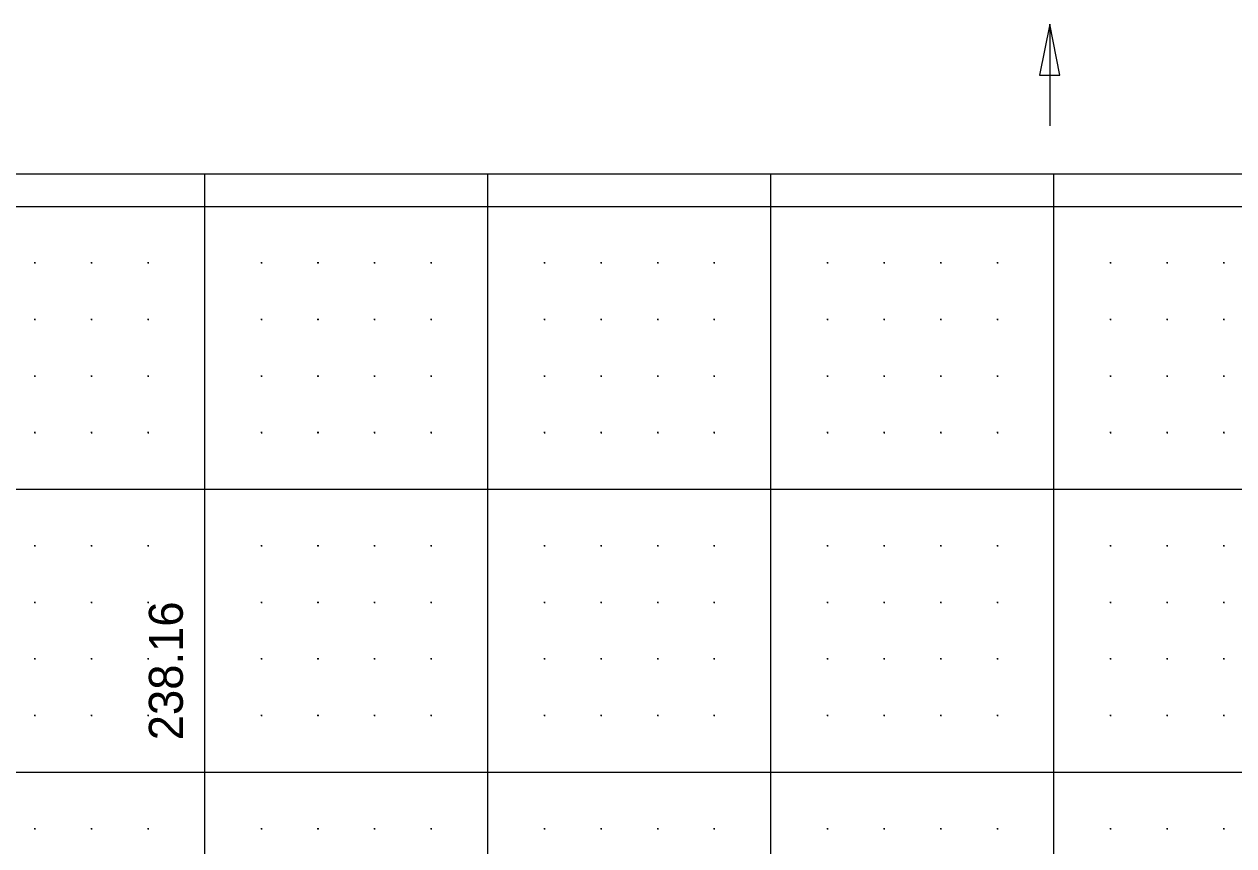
# Model space of a CAD drawing. Extents: x -80 to 80, y 222 to 253.
# Drawn here: x 36.81 to 58.18, y 238.7 to 253.22 of the extents above; entities that cross this region are included whole.
import ezdxf

# ---------------------------------------------------------------- set-up
doc = ezdxf.new("R2010")
doc.units = 0
for name, color, linetype in [('DSN_DRFT_XS Border Grid', 7, 'Continuous'), ('DSN_DRFT_XS Grid Major', 7, 'Continuous'), ('DSN_DRFT_XS Grid Minor', 7, 'Continuous'), ('DSN_RDWY_Flow Arrow', 7, 'Continuous'), ('DSN_RDWY_XS Annotation', 7, 'Continuous')]:
    doc.layers.add(name, color=color, linetype=linetype)

msp = doc.modelspace()

# ---------------------------------------------------------------- linework, layer by layer
at = {"layer": 'DSN_DRFT_XS Border Grid'}
msp.add_line((-77.5, 250.573), (77.5, 250.573), dxfattribs=at)
at = {"layer": 'DSN_DRFT_XS Grid Major'}
for p, q in [((40, 226), (40, 250.573)), ((45, 226), (45, 250.573)), ((50, 226), (50, 250.573)), ((55, 226), (55, 250.573)), ((-77.5, 250), (77.5, 250)), ((-77.5, 245), (77.5, 245)), ((-77.5, 240), (77.5, 240))]:
    msp.add_line(p, q, dxfattribs=at)
at = {"layer": 'DSN_DRFT_XS Grid Minor'}
for p, q in [((37.012, 249), (36.988, 249)), ((37, 249.012), (37, 248.988)), ((38.012, 249), (37.988, 249)), ((38, 249.012), (38, 248.988)), ((39.012, 249), (38.988, 249)), ((39, 249.012), (39, 248.988)), ((41.012, 249), (40.988, 249)), ((41, 249.012), (41, 248.988)), ((42.012, 249), (41.988, 249)), ((42, 249.012), (42, 248.988)), ((43.012, 249), (42.988, 249)), ((43, 249.012), (43, 248.988)), ((44.012, 249), (43.988, 249)), ((44, 249.012), (44, 248.988)), ((46.012, 249), (45.988, 249)), ((46, 249.012), (46, 248.988)), ((47.012, 249), (46.988, 249)), ((47, 249.012), (47, 248.988)), ((48.012, 249), (47.988, 249)), ((48, 249.012), (48, 248.988)), ((49.012, 249), (48.988, 249)), ((49, 249.012), (49, 248.988)), ((51.012, 249), (50.988, 249)), ((51, 249.012), (51, 248.988)), ((52.012, 249), (51.988, 249)), ((52, 249.012), (52, 248.988)), ((53.012, 249), (52.988, 249)), ((53, 249.012), (53, 248.988)), ((54.012, 249), (53.988, 249)), ((54, 249.012), (54, 248.988)), ((56.012, 249), (55.988, 249)), ((56, 249.012), (56, 248.988)), ((57.012, 249), (56.988, 249)), ((57, 249.012), (57, 248.988)), ((58.012, 249), (57.988, 249)), ((58, 249.012), (58, 248.988)), ((37.012, 248), (36.988, 248)), ((37, 248.012), (37, 247.988)), ((38.012, 248), (37.988, 248)), ((38, 248.012), (38, 247.988)), ((39.012, 248), (38.988, 248)), ((39, 248.012), (39, 247.988)), ((41.012, 248), (40.988, 248)), ((41, 248.012), (41, 247.988)), ((42.012, 248), (41.988, 248)), ((42, 248.012), (42, 247.988)), ((43.012, 248), (42.988, 248)), ((43, 248.012), (43, 247.988)), ((44.012, 248), (43.988, 248)), ((44, 248.012), (44, 247.988)), ((46.012, 248), (45.988, 248)), ((46, 248.012), (46, 247.988)), ((47.012, 248), (46.988, 248)), ((47, 248.012), (47, 247.988)), ((48.012, 248), (47.988, 248)), ((48, 248.012), (48, 247.988)), ((49.012, 248), (48.988, 248)), ((49, 248.012), (49, 247.988)), ((51.012, 248), (50.988, 248)), ((51, 248.012), (51, 247.988)), ((52.012, 248), (51.988, 248)), ((52, 248.012), (52, 247.988)), ((53.012, 248), (52.988, 248)), ((53, 248.012), (53, 247.988)), ((54.012, 248), (53.988, 248)), ((54, 248.012), (54, 247.988)), ((56.012, 248), (55.988, 248)), ((56, 248.012), (56, 247.988)), ((57.012, 248), (56.988, 248)), ((57, 248.012), (57, 247.988)), ((58.012, 248), (57.988, 248)), ((58, 248.012), (58, 247.988)), ((37.012, 247), (36.988, 247)), ((37, 247.012), (37, 246.988)), ((38.012, 247), (37.988, 247)), ((38, 247.012), (38, 246.988)), ((39.012, 247), (38.988, 247)), ((39, 247.012), (39, 246.988)), ((41.012, 247), (40.988, 247)), ((41, 247.012), (41, 246.988)), ((42.012, 247), (41.988, 247)), ((42, 247.012), (42, 246.988)), ((43.012, 247), (42.988, 247)), ((43, 247.012), (43, 246.988)), ((44.012, 247), (43.988, 247)), ((44, 247.012), (44, 246.988)), ((46.012, 247), (45.988, 247)), ((46, 247.012), (46, 246.988)), ((47.012, 247), (46.988, 247)), ((47, 247.012), (47, 246.988)), ((48.012, 247), (47.988, 247)), ((48, 247.012), (48, 246.988)), ((49.012, 247), (48.988, 247)), ((49, 247.012), (49, 246.988)), ((51.012, 247), (50.988, 247)), ((51, 247.012), (51, 246.988)), ((52.012, 247), (51.988, 247)), ((52, 247.012), (52, 246.988)), ((53.012, 247), (52.988, 247)), ((53, 247.012), (53, 246.988)), ((54.012, 247), (53.988, 247)), ((54, 247.012), (54, 246.988)), ((56.012, 247), (55.988, 247)), ((56, 247.012), (56, 246.988)), ((57.012, 247), (56.988, 247)), ((57, 247.012), (57, 246.988)), ((58.012, 247), (57.988, 247)), ((58, 247.012), (58, 246.988)), ((37.012, 246), (36.988, 246)), ((37, 246.012), (37, 245.988)), ((38.012, 246), (37.988, 246)), ((38, 246.012), (38, 245.988)), ((39.012, 246), (38.988, 246)), ((39, 246.012), (39, 245.988)), ((41.012, 246), (40.988, 246)), ((41, 246.012), (41, 245.988)), ((42.012, 246), (41.988, 246)), ((42, 246.012), (42, 245.988)), ((43.012, 246), (42.988, 246)), ((43, 246.012), (43, 245.988)), ((44.012, 246), (43.988, 246)), ((44, 246.012), (44, 245.988)), ((46.012, 246), (45.988, 246)), ((46, 246.012), (46, 245.988)), ((47.012, 246), (46.988, 246)), ((47, 246.012), (47, 245.988)), ((48.012, 246), (47.988, 246)), ((48, 246.012), (48, 245.988)), ((49.012, 246), (48.988, 246)), ((49, 246.012), (49, 245.988)), ((51.012, 246), (50.988, 246)), ((51, 246.012), (51, 245.988)), ((52.012, 246), (51.988, 246)), ((52, 246.012), (52, 245.988)), ((53.012, 246), (52.988, 246)), ((53, 246.012), (53, 245.988)), ((54.012, 246), (53.988, 246)), ((54, 246.012), (54, 245.988)), ((56.012, 246), (55.988, 246)), ((56, 246.012), (56, 245.988)), ((57.012, 246), (56.988, 246)), ((57, 246.012), (57, 245.988)), ((58.012, 246), (57.988, 246)), ((58, 246.012), (58, 245.988)), ((37.012, 244), (36.988, 244)), ((37, 244.012), (37, 243.988)), ((38.012, 244), (37.988, 244)), ((38, 244.012), (38, 243.988)), ((39.012, 244), (38.988, 244)), ((39, 244.012), (39, 243.988)), ((41.012, 244), (40.988, 244)), ((41, 244.012), (41, 243.988)), ((42.012, 244), (41.988, 244)), ((42, 244.012), (42, 243.988)), ((43.012, 244), (42.988, 244)), ((43, 244.012), (43, 243.988)), ((44.012, 244), (43.988, 244)), ((44, 244.012), (44, 243.988)), ((46.012, 244), (45.988, 244)), ((46, 244.012), (46, 243.988)), ((47.012, 244), (46.988, 244)), ((47, 244.012), (47, 243.988)), ((48.012, 244), (47.988, 244)), ((48, 244.012), (48, 243.988)), ((49.012, 244), (48.988, 244)), ((49, 244.012), (49, 243.988)), ((51.012, 244), (50.988, 244)), ((51, 244.012), (51, 243.988)), ((52.012, 244), (51.988, 244)), ((52, 244.012), (52, 243.988)), ((53.012, 244), (52.988, 244)), ((53, 244.012), (53, 243.988)), ((54.012, 244), (53.988, 244)), ((54, 244.012), (54, 243.988)), ((56.012, 244), (55.988, 244)), ((56, 244.012), (56, 243.988)), ((57.012, 244), (56.988, 244)), ((57, 244.012), (57, 243.988)), ((58.012, 244), (57.988, 244)), ((58, 244.012), (58, 243.988)), ((37.012, 243), (36.988, 243)), ((37, 243.012), (37, 242.988)), ((38.012, 243), (37.988, 243)), ((38, 243.012), (38, 242.988)), ((39.012, 243), (38.988, 243)), ((39, 243.012), (39, 242.988)), ((41.012, 243), (40.988, 243)), ((41, 243.012), (41, 242.988)), ((42.012, 243), (41.988, 243)), ((42, 243.012), (42, 242.988)), ((43.012, 243), (42.988, 243)), ((43, 243.012), (43, 242.988)), ((44.012, 243), (43.988, 243)), ((44, 243.012), (44, 242.988)), ((46.012, 243), (45.988, 243)), ((46, 243.012), (46, 242.988)), ((47.012, 243), (46.988, 243)), ((47, 243.012), (47, 242.988)), ((48.012, 243), (47.988, 243)), ((48, 243.012), (48, 242.988)), ((49.012, 243), (48.988, 243)), ((49, 243.012), (49, 242.988)), ((51.012, 243), (50.988, 243)), ((51, 243.012), (51, 242.988)), ((52.012, 243), (51.988, 243)), ((52, 243.012), (52, 242.988)), ((53.012, 243), (52.988, 243)), ((53, 243.012), (53, 242.988)), ((54.012, 243), (53.988, 243)), ((54, 243.012), (54, 242.988)), ((56.012, 243), (55.988, 243)), ((56, 243.012), (56, 242.988)), ((57.012, 243), (56.988, 243)), ((57, 243.012), (57, 242.988)), ((58.012, 243), (57.988, 243)), ((58, 243.012), (58, 242.988)), ((37.012, 242), (36.988, 242)), ((37, 242.012), (37, 241.988)), ((38.012, 242), (37.988, 242)), ((38, 242.012), (38, 241.988)), ((39.012, 242), (38.988, 242)), ((39, 242.012), (39, 241.988)), ((41.012, 242), (40.988, 242)), ((41, 242.012), (41, 241.988)), ((42.012, 242), (41.988, 242)), ((42, 242.012), (42, 241.988)), ((43.012, 242), (42.988, 242)), ((43, 242.012), (43, 241.988)), ((44.012, 242), (43.988, 242)), ((44, 242.012), (44, 241.988)), ((46.012, 242), (45.988, 242)), ((46, 242.012), (46, 241.988)), ((47.012, 242), (46.988, 242)), ((47, 242.012), (47, 241.988)), ((48.012, 242), (47.988, 242)), ((48, 242.012), (48, 241.988)), ((49.012, 242), (48.988, 242)), ((49, 242.012), (49, 241.988)), ((51.012, 242), (50.988, 242)), ((51, 242.012), (51, 241.988)), ((52.012, 242), (51.988, 242)), ((52, 242.012), (52, 241.988)), ((53.012, 242), (52.988, 242)), ((53, 242.012), (53, 241.988)), ((54.012, 242), (53.988, 242)), ((54, 242.012), (54, 241.988)), ((56.012, 242), (55.988, 242)), ((56, 242.012), (56, 241.988)), ((57.012, 242), (56.988, 242)), ((57, 242.012), (57, 241.988)), ((58.012, 242), (57.988, 242)), ((58, 242.012), (58, 241.988)), ((37, 241.012), (37, 240.988)), ((38, 241.012), (38, 240.988)), ((39, 241.012), (39, 240.988)), ((41, 241.012), (41, 240.988)), ((42, 241.012), (42, 240.988)), ((43, 241.012), (43, 240.988)), ((44, 241.012), (44, 240.988)), ((46, 241.012), (46, 240.988)), ((47, 241.012), (47, 240.988)), ((48, 241.012), (48, 240.988)), ((49, 241.012), (49, 240.988)), ((51, 241.012), (51, 240.988)), ((52, 241.012), (52, 240.988)), ((53, 241.012), (53, 240.988)), ((54, 241.012), (54, 240.988)), ((56, 241.012), (56, 240.988)), ((57, 241.012), (57, 240.988)), ((58, 241.012), (58, 240.988)), ((37.012, 241), (36.988, 241)), ((38.012, 241), (37.988, 241)), ((39.012, 241), (38.988, 241)), ((41.012, 241), (40.988, 241)), ((42.012, 241), (41.988, 241)), ((43.012, 241), (42.988, 241)), ((44.012, 241), (43.988, 241)), ((46.012, 241), (45.988, 241)), ((47.012, 241), (46.988, 241)), ((48.012, 241), (47.988, 241)), ((49.012, 241), (48.988, 241)), ((51.012, 241), (50.988, 241)), ((52.012, 241), (51.988, 241)), ((53.012, 241), (52.988, 241)), ((54.012, 241), (53.988, 241)), ((56.012, 241), (55.988, 241)), ((57.012, 241), (56.988, 241)), ((58.012, 241), (57.988, 241)), ((37.012, 239), (36.988, 239)), ((37, 239.012), (37, 238.988)), ((38.012, 239), (37.988, 239)), ((38, 239.012), (38, 238.988)), ((39.012, 239), (38.988, 239)), ((39, 239.012), (39, 238.988)), ((41.012, 239), (40.988, 239)), ((41, 239.012), (41, 238.988)), ((42.012, 239), (41.988, 239)), ((42, 239.012), (42, 238.988)), ((43.012, 239), (42.988, 239)), ((43, 239.012), (43, 238.988)), ((44.012, 239), (43.988, 239)), ((44, 239.012), (44, 238.988)), ((46.012, 239), (45.988, 239)), ((46, 239.012), (46, 238.988)), ((47.012, 239), (46.988, 239)), ((47, 239.012), (47, 238.988)), ((48.012, 239), (47.988, 239)), ((48, 239.012), (48, 238.988)), ((49.012, 239), (48.988, 239)), ((49, 239.012), (49, 238.988)), ((51.012, 239), (50.988, 239)), ((51, 239.012), (51, 238.988)), ((52.012, 239), (51.988, 239)), ((52, 239.012), (52, 238.988)), ((53.012, 239), (52.988, 239)), ((53, 239.012), (53, 238.988)), ((54.012, 239), (53.988, 239)), ((54, 239.012), (54, 238.988)), ((56.012, 239), (55.988, 239)), ((56, 239.012), (56, 238.988)), ((57.012, 239), (56.988, 239)), ((57, 239.012), (57, 238.988)), ((58.012, 239), (57.988, 239)), ((58, 239.012), (58, 238.988))]:
    msp.add_line(p, q, dxfattribs=at)
at = {"layer": 'DSN_RDWY_Flow Arrow'}
msp.add_lwpolyline([(54.926, 253.22), (54.746, 252.32), (55.106, 252.32), (54.926, 253.22), (54.926, 251.42)], dxfattribs=at)

# ---------------------------------------------------------------- texts
at = {"layer": 'DSN_RDWY_XS Annotation'}
msp.add_text('238.16', height=0.6, rotation=90, dxfattribs=at).set_placement((39.613, 240.563))

doc.saveas('drawing.dxf')
